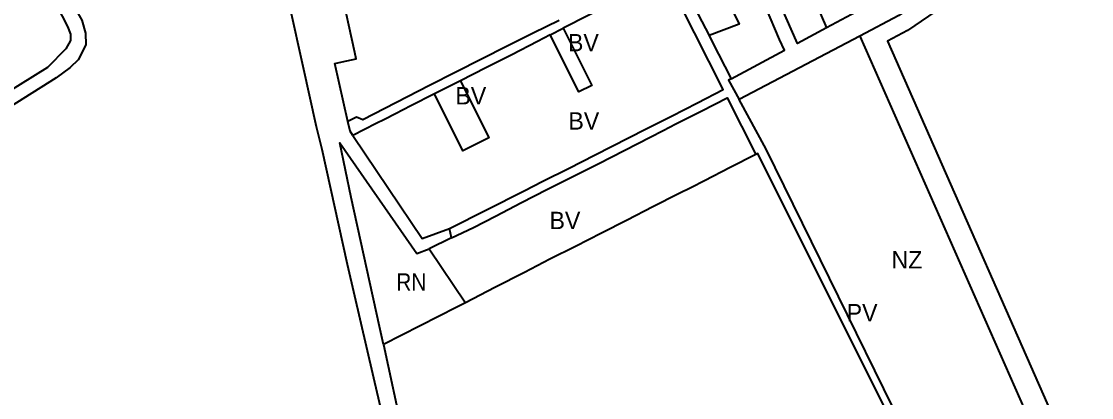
# Model space of a CAD drawing. Extents: x -650451 to -642268, y -1075216 to -1066610.
# Drawn here: x -648982 to -648056, y -1068079 to -1067753 of the extents above; entities that cross this region are included whole.
import ezdxf

# ---------------------------------------------------------------- set-up
doc = ezdxf.new("R2010")
doc.units = 0
doc.header["$LTSCALE"] = 6
doc.layers.add('1', color=7, linetype='Continuous', lineweight=35)
doc.layers.add('2', color=7, linetype='Continuous')
doc.layers.add('3', color=7, linetype='Continuous')

msp = doc.modelspace()

# ---------------------------------------------------------------- linework, layer by layer
at = {"layer": '1'}
for p, q in [((-648524.44, -1067765.11), (-648513.23, -1067759.38)), ((-648256.499, -1067766.091), (-648360.993, -1067821.027)), ((-648602.3, -1067804.83), (-648624.76, -1067816.11)), ((-648609.91, -1067940.58), (-648611.61, -1067932.63))]:
    msp.add_line(p, q, dxfattribs=at)
for points in [[(-648827.86, -1067465.86), (-649043.58, -1067537.95), (-649051.36, -1067541.81), (-649056.25, -1067548.45), (-649054.62, -1067560), (-649040.88, -1067579.35), (-649014.81, -1067616.11), (-648989.29, -1067652.07), (-648961.65, -1067698.67), (-648935.54, -1067742.7), (-648929.93, -1067752.22), (-648926.79, -1067763.65), (-648926.42, -1067773.69), (-648933.16, -1067786.77), (-648940.02, -1067793.41), (-648952.15, -1067802.08), (-649118.66, -1067906.86), (-649165.63, -1067937.14), (-649203.19, -1067963.4), (-649376.467, -1068081.552)], [(-648827.86, -1067465.86), (-648813.94, -1067506.27), (-648804.08, -1067534.88), (-648792.97, -1067537.86), (-648791.68, -1067543.78), (-648767.84, -1067652.98), (-648749.97, -1067741.49), (-648738.7, -1067792.04), (-648727.05, -1067844.33), (-648722.09, -1067863.84), (-648700.16, -1067963.42), (-648677.61, -1068061.74), (-648662.71, -1068124.76), (-648655.88, -1068153.63), (-648634.84, -1068248.76), (-648615.87, -1068327.3), (-648594.38, -1068425.02), (-648573.96, -1068518.34), (-648572.95, -1068522.97), (-648561.032, -1068578.982), (-648566.33, -1068582.22), (-648579.97, -1068587.39), (-648580.062, -1068590.087)], [(-648367.811, -1067802.994), (-648321.623, -1067778.399), (-648326, -1067769), (-648337.32, -1067742.59), (-648348.55, -1067716.71), (-648359.6, -1067691.58), (-648371.34, -1067665.08), (-648386.91, -1067634.83), (-648417.12, -1067576.17), (-648443.83, -1067589.92)], [(-648443.83, -1067589.92), (-648428.7, -1067619.24), (-648397.98, -1067678.79), (-648388.506, -1067698.645), (-648373.99, -1067728.95), (-648361.08, -1067755.88), (-648387.04, -1067765.67)], [(-648470.47, -1067603.64), (-648455.98, -1067633.3), (-648440.25, -1067662.32), (-648399.58, -1067741.31), (-648387.04, -1067765.67)], [(-647988.334, -1067619.747), (-648110.36, -1067673.133), (-648146.127, -1067695.8), (-648222.872, -1067748.412), (-648256.499, -1067766.091)], [(-648342.697, -1067626.806), (-648342.023, -1067628.096), (-648285.254, -1067759.009)], [(-647980.561, -1067632.719), (-648103.298, -1067686.416), (-648137.869, -1067708.325), (-648215.115, -1067761.28), (-648232.676, -1067770.513), (-648061.329, -1068158.649), (-647982.969, -1068116.575), (-647971.35, -1068144.48), (-647929.45, -1068244.16)], [(-648285.254, -1067759.009), (-648310.511, -1067772.476), (-648359.213, -1067661.956), (-648369.949, -1067640.851)], [(-648997.32, -1067662.6), (-648978.53, -1067694.76), (-648952.34, -1067739.61), (-648947.01, -1067748.74), (-648942.46, -1067757.73), (-648939.93, -1067764.54), (-648939.85, -1067770), (-648943.93, -1067777.06), (-648959.69, -1067793.21), (-649123.43, -1067894.75)], [(-648611.61, -1067932.63), (-648547.09, -1067899.87), (-648530.81, -1067891.61), (-648508.22, -1067880.38), (-648486.09, -1067868.98), (-648441.47, -1067846.37), (-648419.44, -1067835.3), (-648397.04, -1067823.85), (-648374.84, -1067812.43), (-648399.64, -1067763.26), (-648424.14, -1067714.34), (-648435.34, -1067720.01), (-648446.58, -1067725.71), (-648468.97, -1067736.91), (-648480.06, -1067742.47), (-648491.14, -1067748.02), (-648513.23, -1067759.38)], [(-648699.593, -1067840.046), (-648710.96, -1067789.91), (-648704.614, -1067788.491), (-648692.53, -1067785.79), (-648693.78, -1067780.24), (-648706.08, -1067723.56)], [(-648262.63, -1067726.71), (-648262.632, -1067726.711), (-648255.016, -1067742.886), (-648285.254, -1067759.009)], [(-648516.73, -1067752.57), (-648539.31, -1067763.71), (-648561.71, -1067774.93), (-648584.13, -1067786.06), (-648606.09, -1067797.19), (-648628.99, -1067808.91), (-648686.7, -1067838.45), (-648692.08, -1067836.26), (-648699.59, -1067840.06), (-648699.593, -1067840.046)], [(-648524.44, -1067765.11), (-648535.61, -1067770.85), (-648557.84, -1067782.26), (-648580.14, -1067793.61), (-648602.3, -1067804.83)], [(-648513.23, -1067759.38), (-648488.49, -1067808.76), (-648499.7, -1067814.37), (-648524.44, -1067765.11)], [(-648387.04, -1067765.67), (-648384.25, -1067771.07), (-648367.811, -1067802.994)], [(-648256.499, -1067766.091), (-648079.002, -1068168.139), (-648165.28, -1068214.465)], [(-648602.3, -1067804.83), (-648577.78, -1067854.07), (-648600.14, -1067865.29), (-648624.76, -1067816.11)], [(-648367.811, -1067802.994), (-648370.113, -1067804.22), (-648360.993, -1067821.027)], [(-648624.76, -1067816.11), (-648645.11, -1067826.48), (-648658.42, -1067833.26), (-648668.085, -1067838.186), (-648675.26, -1067841.84), (-648695.27, -1067852.04)], [(-648609.91, -1067940.58), (-648591.04, -1067931.62), (-648571.88, -1067921.71), (-648549.44, -1067910.07), (-648527.33, -1067898.74), (-648504.92, -1067887.52), (-648482.5, -1067876.22), (-648437.89, -1067853.4), (-648426.65, -1067847.64), (-648415.69, -1067841.98), (-648393.35, -1067830.81), (-648371.27, -1067819.47), (-648346.57, -1067868.56)], [(-648165.28, -1068214.465), (-648337.67, -1067864.01), (-648360.993, -1067821.027)], [(-648695.27, -1067852.04), (-648697.7, -1067848.43), (-648699.621, -1067840.06), (-648699.593, -1067840.046)], [(-648695.27, -1067852.04), (-648664.41, -1067897.91), (-648635.249, -1067941.252), (-648611.61, -1067932.63)], [(-648668.92, -1068032.96), (-648672.31, -1068017.25), (-648696.93, -1067905.76), (-648706.687, -1067858.345), (-648640, -1067954), (-648629.22, -1067950.214)], [(-648346.57, -1067868.56), (-648368.78, -1067879.75), (-648391.08, -1067891.24), (-648402.29, -1067897.02), (-648413.41, -1067902.53), (-648435.55, -1067913.84), (-648457.87, -1067925.4), (-648480.12, -1067936.55), (-648502.59, -1067948), (-648524.72, -1067958.93), (-648546.76, -1067970.44), (-648572.5, -1067983.59), (-648597.93, -1067996.72)], [(-648112.198, -1068333.037), (-648344.79, -1067867.65), (-648346.57, -1067868.56)], [(-648609.91, -1067940.58), (-648629.22, -1067950.214), (-648597.93, -1067996.72)], [(-648597.93, -1067996.72), (-648605.323, -1068000.463), (-648668.92, -1068032.96)], [(-648668.92, -1068032.96), (-648651.89, -1068111.95), (-648649.74, -1068121.95), (-648644.73, -1068145.27), (-648630.99, -1068209.19), (-648610.14, -1068304.32), (-648587.39, -1068405.82), (-648559.91, -1068532.62), (-648551.041, -1068573.16)]]:
    msp.add_lwpolyline(points, dxfattribs=at)

# ---------------------------------------------------------------- texts
at = {"layer": '2'}
for s, p in [('BV', (-648509.181, -1067779.274)), ('BV', (-648606.637, -1067825.223)), ('NZ', (-648229.056, -1067967.053)), ('PV', (-648267.925, -1068012.813))]:
    msp.add_text(s, height=15, dxfattribs=at).set_placement(p)
at = {"layer": '3'}
for p in [(-648508.795, -1067846.967), (-648525.155, -1067933.038)]:
    msp.add_text('BV', height=15, dxfattribs=at).set_placement(p)
at = {"layer": '3', "width": 0.9}
msp.add_text('RN', height=15, dxfattribs=at).set_placement((-648657.801, -1067986.251))

doc.saveas('drawing.dxf')
